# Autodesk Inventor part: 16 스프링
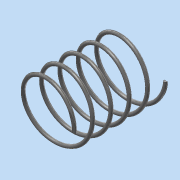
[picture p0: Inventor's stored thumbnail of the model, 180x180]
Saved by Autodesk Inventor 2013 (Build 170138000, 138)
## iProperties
Created: 2016-06
Part Number: 16 스프링
Material: 강철, 탄소
Document SubType Name: Modeling
Designer: Administrator
Density: 7.87 g/cm^3
Mass: 1.6371 g
Surface Area: 8.38376 cm^2
Volume: 0.208018 cm^3
Author: Administrator
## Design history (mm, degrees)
sketch "스케치1"
  geometry: L1 (0, 0)-(8.5, 0); L2 (8.5, 0)-(8.5, 26); L3 (8.5, 26)-(0, 26); L4 (0, 26)-(0, 0); C1 r 0.5 at (8.5, 0)
  constraints: 8 end point, 2 parallel, 1 centre point, 1 coincident, 1 horizontal, 1 perpendicular
  dimensions: "d0" = 26 distance of L3.end L1.start (derived); "d1" = 1 diameter of C1; "d2" = 17 diameter of L2 L4
feature "코일1" sketch "스케치1" pitch "d3" = 10; turns "d5" = 5; dims "d4" = 26 (= d0), "d6" = 0, angle "d7" = 90 deg, angle "d8" = 90 deg, "d9" = 0, "d10" = 0
sketch "스케치2"
  geometry: L1 (0, 15)-(26, 15); L2 (26, 15)-(26, -15); L3 (26, -15)-(0, -15); L4 (0, -15)-(0, 15); 4 further points
  constraints: 8 end point, 2 coincident, 2 midpoint, 2 parallel, 1 horizontal, 1 perpendicular
  dimensions: "d11" = 30 distance of L1.end L2.end
extrude "돌출1" sketch "스케치2" stored distance "d13" = 50; taper "d14" = 0 deg
node "솔리드1"
